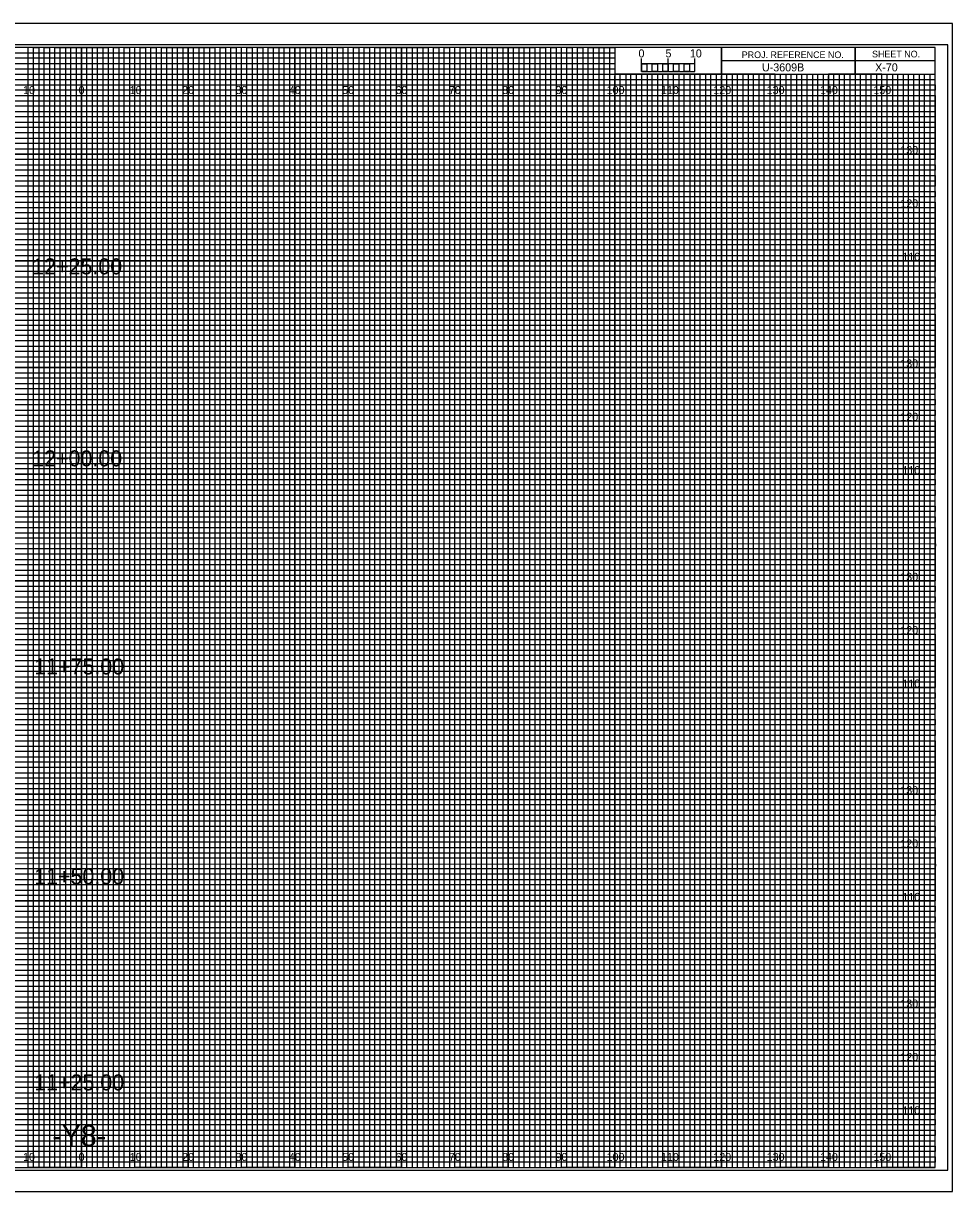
# Model space of a CAD drawing. Extents: x -13 to 323, y -5 to 434.
# Drawn here: x 149.1 to 323.3, y -4.5 to 214.5 of the extents above; entities that cross this region are included whole.
import ezdxf

# ---------------------------------------------------------------- set-up
doc = ezdxf.new("R2010")
doc.units = 0
for name, color, linetype in [('Exist CMT Pavement', 7, 'Continuous'), ('Exist Cross Section Cell', 7, 'Continuous'), ('Exist XS Center Line Elevation Label', 7, 'Continuous'), ('Exist XS Ground Line', 7, 'Continuous'), ('Prop CMT Pvmt Course 1 Wedge', 7, 'Continuous'), ('Prop CMT Pvmt Course 2', 7, 'Continuous'), ('Prop CMT Pvmt Course 2 Wedge', 7, 'Continuous'), ('Prop CMT Pvmt Course 3', 7, 'Continuous'), ('Prop CMT Pvmt Course 3 Wedge', 7, 'Continuous'), ('Prop CMT Pvmt Surface', 7, 'Continuous'), ('Prop CMT Pvmt Wedge Surface 1', 7, 'Continuous'), ('Prop CMT Pvmt Wedge Surface 2', 7, 'Continuous'), ('Prop CMT Shld Paved Course 1', 7, 'Continuous'), ('Prop CMT Shld Paved Course 2', 7, 'Continuous'), ('Prop CMT Shld Paved Course 3', 7, 'Continuous'), ('Prop CMT Subgrade Earthwork', 7, 'Continuous'), ('Scratch_Level_0', 7, 'Continuous')]:
    doc.layers.add(name, color=color, linetype=linetype)

msp = doc.modelspace()

# ---------------------------------------------------------------- linework, layer by layer
at = {"layer": 'Exist XS Center Line Elevation Label'}
for points in [[(145, 0), (155, 0), (155, 210), (165, 210), (165, 0), (175, 0), (175, 210), (185, 210), (185, 0), (195, 0), (195, 210), (205, 210), (205, 0), (215, 0), (215, 210), (225, 210), (225, 0), (235, 0), (235, 210), (245, 210), (245, 0), (255, 0), (255, 210), (259.93, 210), (260, 210), (260, 205), (264.99, 205), (264.99, 0), (275, 0), (275, 205), (285, 205), (285, 0), (295, 0), (295, 205), (305, 205), (305, 0), (315, 0), (315, 205)], [(0, 205), (275, 205)], [(0, 185), (320, 185), (320, 195), (0, 195)], [(0, 165), (320, 165), (320, 175), (0, 175)], [(0, 145), (320, 145), (320, 155), (0, 155)], [(0, 125), (320, 125), (320, 135), (0, 135)], [(0, 105), (320, 105), (320, 115), (0, 115)], [(0, 85), (320, 85), (320, 95), (0, 95)], [(0, 65), (320, 65), (320, 75), (0, 75)], [(0, 45), (320, 45), (320, 55), (0, 55)], [(0, 25), (320, 25), (320, 35), (0, 35)], [(0, 5), (320, 5), (320, 15), (0, 15)]]:
    msp.add_lwpolyline(points, dxfattribs=at)
at = {"layer": 'Exist XS Ground Line'}
for p, q in [((150, 210), (140, 210)), ((150, 0), (150, 210)), ((170, 210), (160, 210)), ((160, 210), (160, 0)), ((170, 0), (170, 210)), ((190, 210), (180, 210)), ((180, 210), (180, 0)), ((190, 0), (190, 210)), ((210, 210), (200, 210)), ((200, 210), (200, 0)), ((210, 0), (210, 210)), ((230, 210), (220, 210)), ((220, 210), (220, 0)), ((230, 0), (230, 210)), ((250, 210), (240, 210)), ((240, 210), (240, 0)), ((250, 0), (250, 210)), ((260, 210), (260, 0)), ((270, 0), (270, 205)), ((290, 205), (280, 205)), ((280, 205), (280, 0)), ((290, 0), (290, 205)), ((310, 205), (300, 205)), ((300, 205), (300, 0)), ((310, 0), (310, 205)), ((160, 0), (150, 0)), ((180, 0), (170, 0)), ((200, 0), (190, 0)), ((220, 0), (210, 0)), ((240, 0), (230, 0)), ((260, 0), (250, 0)), ((280, 0), (270, 0)), ((300, 0), (290, 0)), ((320, 0), (310, 0)), ((320, 0), (320, 0))]:
    msp.add_line(p, q, dxfattribs=at)
for points in [[(0, 200), (320, 200), (320, 190), (0, 190)], [(0, 180), (320, 180), (320, 170), (0, 170)], [(0, 160), (320, 160), (320, 150), (0, 150)], [(0, 140), (320, 140), (320, 130), (0, 130)], [(0, 120), (320, 120), (320, 110), (0, 110)], [(0, 100), (320, 100), (320, 90), (0, 90)], [(0, 80), (320, 80), (320, 70), (0, 70)], [(0, 60), (320, 60), (320, 50), (0, 50)], [(0, 40), (320, 40), (320, 30), (0, 30)], [(0, 20), (320, 20), (320, 10), (0, 10)]]:
    msp.add_lwpolyline(points, dxfattribs=at)
at = {"layer": 'Prop CMT Pvmt Course 1 Wedge'}
for p, q in [((323.3, 214.5), (-13.4, 214.5)), ((-13.4, -4.5), (323.3, -4.5))]:
    msp.add_line(p, q, dxfattribs=at)
at = {"layer": 'Prop CMT Pvmt Course 2'}
msp.add_lwpolyline([(-13.4, -4.5), (323.3, -4.5), (323.3, 214.5), (-13.4, 214.5)], close=True, dxfattribs=at)
at = {"layer": 'Prop CMT Pvmt Course 3'}
msp.add_lwpolyline([(-10.8, -0.5), (322.4, -0.5), (322.4, 210.5), (-10.8, 210.5)], close=True, dxfattribs=at)
at = {"layer": 'Prop CMT Shld Paved Course 1'}
for p, q in [((305, 210), (305, 205)), ((305, 205), (305, 210)), ((280, 207.5), (280, 205)), ((320, 207.49), (280, 207.49)), ((280, 205), (320, 205))]:
    msp.add_line(p, q, dxfattribs=at)
for points in [[(320, 210), (0, 210), (0, 0), (320, 0)], [(280, 210), (260, 210), (260, 205.03), (280, 205.03)], [(320, 210), (280, 210), (280, 205), (320, 205)]]:
    msp.add_lwpolyline(points, close=True, dxfattribs=at)
at = {"layer": 'Prop CMT Shld Paved Course 2'}
for p, q in [((267, 205), (266.01, 205)), ((266.01, 205), (266.01, 0)), ((267, 0), (267, 205)), ((269, 205), (268, 205)), ((268, 205), (268, 0)), ((269, 0), (269, 205)), ((266.01, 0), (265, 0)), ((268, 0), (267, 0))]:
    msp.add_line(p, q, dxfattribs=at)
for points in [[(150, 0), (151, 0), (151, 210), (152, 210), (152, 0)], [(152, 0), (153, 0), (153, 210), (154, 210), (154, 0)], [(155, 0), (156, 0), (156, 210), (157, 210), (157, 0)], [(157, 0), (158, 0), (158, 210), (159, 210), (159, 0)], [(160, 0), (161, 0), (161, 210), (162, 210), (162, 0)], [(162, 0), (163, 0), (163, 210), (164, 210), (164, 0)], [(165, 0), (166, 0), (166, 210), (167, 210), (167, 0)], [(167, 0), (168, 0), (168, 210), (169, 210), (169, 0)], [(170, 0), (171, 0), (171, 210), (172, 210), (172, 0)], [(172, 0), (173, 0), (173, 210), (174, 210), (174, 0)], [(175, 0), (176, 0), (176, 210), (177, 210), (177, 0)], [(177, 0), (178, 0), (178, 210), (179, 210), (179, 0)], [(180, 0), (181, 0), (181, 210), (182, 210), (182, 0)], [(182, 0), (183, 0), (183, 210), (184, 210), (184, 0)], [(185, 0), (186, 0), (186, 210), (187, 210), (187, 0)], [(187, 0), (188, 0), (188, 210), (189, 210), (189, 0)], [(190, 0), (191, 0), (191, 210), (192, 210), (192, 0)], [(192, 0), (193, 0), (193, 210), (194, 210), (194, 0)], [(195, 0), (196, 0), (196, 210), (197, 210), (197, 0)], [(197, 0), (198, 0), (198, 210), (199, 210), (199, 0)], [(200, 0), (201, 0), (201, 210), (202, 210), (202, 0)], [(202, 0), (203, 0), (203, 210), (204, 210), (204, 0)], [(205, 0), (206, 0), (206, 210), (207, 210), (207, 0)], [(207, 0), (208, 0), (208, 210), (209, 210), (209, 0)], [(210, 0), (211, 0), (211, 210), (212, 210), (212, 0)], [(212, 0), (213, 0), (213, 210), (214, 210), (214, 0)], [(215, 0), (216, 0), (216, 210), (217, 210), (217, 0)], [(217, 0), (218, 0), (218, 210), (219, 210), (219, 0)], [(220, 0), (221, 0), (221, 210), (222, 210), (222, 0)], [(222, 0), (223, 0), (223, 210), (224, 210), (224, 0)], [(225, 0), (226, 0), (226, 210), (227, 210), (227, 0)], [(227, 0), (228, 0), (228, 210), (229, 210), (229, 0)], [(230, 0), (231, 0), (231, 210), (232, 210), (232, 0)], [(232, 0), (233, 0), (233, 210), (234, 210), (234, 0)], [(235, 0), (236, 0), (236, 210), (237, 210), (237, 0)], [(237, 0), (238, 0), (238, 210), (239, 210), (239, 0)], [(240, 0), (241, 0), (241, 210), (242, 210), (242, 0)], [(242, 0), (243, 0), (243, 210), (244, 210), (244, 0)], [(245, 0), (246, 0), (246, 210), (247, 210), (247, 0)], [(247, 0), (248, 0), (248, 210), (249, 210), (249, 0)], [(250, 0), (251, 0), (251, 210), (252, 210), (252, 0)], [(252, 0), (253, 0), (253, 210), (254, 210), (254, 0)], [(255, 0), (256, 0), (256, 210), (257, 210), (257, 0)], [(257, 0), (258, 0), (258, 210), (259, 210), (259, 0)], [(260, 0), (261, 0), (261, 205), (262.02, 205), (262.02, 0)], [(262, 0), (263, 0), (263, 205), (263.99, 205), (263.99, 0)], [(270, 0), (270.98, 0), (270.98, 205), (272, 205), (272, 0)], [(272, 0), (273, 0), (273, 205), (274.05, 205), (274.05, 0)], [(275, 0), (276, 0), (276, 205), (277, 205), (277, 0)], [(277, 0), (278, 0), (278, 205), (279, 205), (279, 0)], [(280, 0), (281, 0), (281, 205), (282, 205), (282, 0)], [(282, 0), (283, 0), (283, 205), (284, 205), (284, 0)], [(285, 0), (286, 0), (286, 205), (287, 205), (287, 0)], [(287, 0), (288, 0), (288, 205), (289, 205), (289, 0)], [(290, 0), (291, 0), (291, 205), (292, 205), (292, 0)], [(292, 0), (293, 0), (293, 205), (294, 205), (294, 0)], [(295, 0), (296, 0), (296, 205), (297, 205), (297, 0)], [(297, 0), (298, 0), (298, 205), (299, 205), (299, 0)], [(300, 0), (301, 0), (301, 205), (302, 205), (302, 0)], [(302, 0), (303, 0), (303, 205), (304, 205), (304, 0)], [(305, 0), (306, 0), (306, 205), (307, 205), (307, 0)], [(307, 0), (308, 0), (308, 205), (309, 205), (309, 0)], [(310, 0), (311, 0), (311, 205), (312, 205), (312, 0)], [(312, 0), (313, 0), (313, 205), (314, 205), (314, 0)], [(315, 0), (316, 0), (316, 205), (317, 205), (317, 0)], [(317, 0), (318, 0), (318, 205), (319, 205), (319, 0)]]:
    msp.add_lwpolyline(points, dxfattribs=at)
at = {"layer": 'Prop CMT Shld Paved Course 3'}
for p, q in [((265, 205.49), (265, 207.9)), ((265, 206.9), (265, 207.9)), ((270, 205.49), (270, 207.9)), ((275, 205.49), (275, 207.9)), ((275, 206.9), (275, 207.9))]:
    msp.add_line(p, q, dxfattribs=at)
for points in [[(275, 206.9), (265, 206.9), (265, 205.49), (275, 205.49)], [(265, 206.9), (266, 206.9), (266, 205.49), (265, 205.49)], [(267, 206.9), (268, 206.9), (268, 205.49), (267, 205.49)], [(269, 206.9), (270, 206.9), (270, 205.49), (269, 205.49)], [(271, 206.9), (272, 206.9), (272, 205.49), (271, 205.49)], [(273, 206.9), (274, 206.9), (274, 205.49), (273, 205.49)]]:
    msp.add_lwpolyline(points, close=True, dxfattribs=at)
at = {"layer": 'Prop CMT Subgrade Earthwork'}
for p, q in [((150, 0), (150, 210)), ((160, 0), (160, 210)), ((170, 0), (170, 210)), ((180, 0), (180, 210)), ((190, 0), (190, 210)), ((200, 0), (200, 210)), ((210, 0), (210, 210)), ((220, 0), (220, 210)), ((230, 0), (230, 210)), ((240, 0), (240, 210)), ((250, 0), (250, 210)), ((260, 0), (260, 204.69)), ((270, 0), (270, 204.69)), ((280, 0), (280, 204.69)), ((290, 0), (290, 204.69)), ((300, 0), (300, 204.69)), ((310, 0), (310, 204.69)), ((0, 200), (320, 200)), ((0, 190), (320, 190)), ((0, 180), (320, 180)), ((0, 170), (320, 170)), ((0, 160), (320, 160)), ((0, 150), (320, 150)), ((0, 140), (320, 140)), ((0, 130), (320, 130)), ((0, 120), (320, 120)), ((0, 110), (320, 110)), ((0, 100), (320, 100)), ((0, 90), (320, 90)), ((0, 80), (320, 80)), ((0, 70), (320, 70)), ((0, 60), (320, 60)), ((0, 50), (320, 50)), ((0, 40), (320, 40)), ((0, 30), (320, 30)), ((0, 20), (320, 20)), ((0, 10), (320, 10))]:
    msp.add_line(p, q, dxfattribs=at)
at = {"layer": 'Scratch_Level_0'}
for p, q in [((0, 209), (260, 209)), ((260, 209), (260, 207.98)), ((260, 207.98), (0, 207.98)), ((0, 207), (260, 207)), ((260, 205.89), (0, 205.89)), ((260, 207), (260, 205.89)), ((0, 204), (320, 204))]:
    msp.add_line(p, q, dxfattribs=at)
for points in [[(0, 203), (270, 203), (320, 203), (320, 202), (0, 202)], [(0, 201), (320, 201), (320, 199), (0, 199)], [(0, 198), (320, 198), (320, 197), (0, 196.98)], [(0, 196), (320, 196), (320, 194), (0, 194)], [(0, 193), (320, 193), (320, 192), (0, 192)], [(0, 191), (320, 191), (320, 189), (0, 189)], [(0, 188), (320, 188), (320, 187), (0, 187)], [(0, 186), (320, 186), (320, 184), (0, 184)], [(0, 183), (320, 183), (320, 182), (0, 182)], [(0, 181), (320, 181), (320, 179), (0, 179)], [(0, 178), (320, 178), (320, 177), (0, 177)], [(0, 176), (320, 176), (320, 173.95), (320, 173), (320, 172), (0, 172)], [(0, 174), (320, 174), (320, 173), (0, 173)], [(0, 171), (320, 171), (320, 169), (0, 169.03)], [(0, 169.03), (320, 169), (320, 168), (0, 168)], [(0, 167), (320, 167), (320, 166), (0, 166)], [(0, 164), (320, 164), (320, 163), (0, 163)], [(0, 162), (320, 162), (320, 161), (0, 161)], [(-0.07, 158.89), (320, 158.89), (320, 157.88), (-0.07, 157.88)], [(0, 157), (320, 157), (320, 156), (0, 156)], [(0, 154), (320, 154), (320, 153), (0, 153)], [(0, 152), (320, 152), (320, 151), (0, 151)], [(0, 149), (320, 149), (320, 148), (0, 148)], [(0, 147), (320, 147), (320, 146), (0, 146)], [(0, 144), (320, 144), (320, 143), (0, 143)], [(0, 142), (320, 142), (320, 141), (0, 141)], [(0, 139), (320, 139), (319.99, 137.98), (0, 138)], [(0, 137), (320, 137), (320, 136), (0, 136)], [(0, 134), (320, 134), (320, 133), (0, 133)], [(0, 132), (320, 132), (320, 131), (0, 131)], [(0, 129), (320, 129), (320, 128), (0, 128)], [(0, 127), (320, 127), (320, 126), (0, 126)], [(0, 124), (320, 124), (320, 123), (0, 123)], [(0, 122), (320, 122), (320, 121), (0, 121)], [(0, 119), (320, 119), (320, 118), (0, 118)], [(0, 116.99), (320.07, 116.91), (320, 116), (0, 116)], [(0, 114), (320, 114), (320, 113), (0, 113)], [(0, 112), (320, 112), (320, 111), (0, 111)], [(0, 109), (320, 109), (320, 108), (0, 108)], [(0, 107), (320, 107), (320, 106), (0, 106)], [(0, 104), (320, 104), (320, 103), (0, 103)], [(0, 102), (320, 102), (320, 101), (0, 101)], [(0, 99), (320, 99), (320, 98), (0, 98)], [(0, 97), (320, 97), (320, 96), (0, 96)], [(0, 94), (320, 94), (320, 93), (0, 93)], [(0, 92), (320, 92), (320, 91), (0, 91)], [(0, 89), (320, 89), (320, 88), (0, 88)], [(0, 87), (320, 87), (320, 86), (0, 86)], [(0, 84), (320, 84), (320, 83), (0, 83)], [(0, 82), (320, 82), (320, 81), (0, 81)], [(0, 79), (320, 79), (319.99, 77.98), (0, 78)], [(0, 77), (320, 77), (320, 76), (0, 76)], [(0, 74), (320, 74), (320, 73), (0, 73)], [(0, 72), (320, 72), (320, 71), (0, 71)], [(0, 69), (320, 69), (320, 68), (0, 68)], [(0, 67), (320, 67), (320, 66), (0, 66)], [(0, 64), (320, 64), (320, 63), (0, 63)], [(0, 62), (320, 62), (320, 61), (0, 61)], [(0, 59), (320, 59), (320, 58), (0, 58)], [(0, 56.99), (320.07, 56.91), (320, 56), (0, 56)], [(0, 54), (320, 54), (320, 53), (0, 53)], [(0, 52), (320, 52), (320, 51), (0, 51)], [(0, 49), (320, 49), (320, 48), (0, 48)], [(0, 47), (320, 47), (320, 46), (0, 46)], [(0, 44), (320, 44), (320, 43), (0, 43)], [(0, 42), (320, 42), (320, 41), (0, 41)], [(0, 39), (320, 39), (320, 38), (0, 38)], [(0, 37), (320, 37), (320, 36), (0, 36)], [(0, 34), (320, 34), (320, 33), (0, 33)], [(0, 32), (320, 32), (320, 31), (0, 31)], [(0, 29), (320, 29), (320, 28), (0, 28)], [(0, 27), (320, 27), (320, 26), (0, 26)], [(0, 24), (320, 24), (320, 23), (0, 23)], [(0, 22), (320, 22), (320, 21), (0, 21)], [(0, 19), (320, 19), (320, 18), (0, 18)], [(0, 17), (320, 17), (320, 16), (0, 16)], [(0, 14), (320, 14), (320, 13), (0, 13)], [(0, 12), (320, 12), (320, 11), (0, 11)], [(0, 9), (320, 9), (320, 8), (0, 8)], [(0, 7), (320, 7), (320, 6), (0, 6)], [(0, 4), (320, 4), (320, 3), (0, 3)], [(0, 2), (320, 2), (320, 1), (0, 1)]]:
    msp.add_lwpolyline(points, dxfattribs=at)

# ---------------------------------------------------------------- texts
at = {"layer": 'Exist CMT Pavement'}
msp.add_text('X-70', height=1.5, dxfattribs=at).set_placement((308.77, 205.5))
at = {"layer": 'Exist Cross Section Cell'}
for s, p in [('10', (149.04, 201.25)), ('0', (159.45, 201.25)), ('0', (159.45, 201.25)), ('10', (169.04, 201.25)), ('20', (178.86, 201.25)), ('30', (188.86, 201.25)), ('40', (198.86, 201.25)), ('50', (208.86, 201.25)), ('60', (218.86, 201.25)), ('70', (228.86, 201.25)), ('80', (238.86, 201.25)), ('90', (248.86, 201.25)), ('100', (258.44, 201.25)), ('110', (268.62, 201.25)), ('120', (278.44, 201.25)), ('130', (288.44, 201.25)), ('140', (298.44, 201.25)), ('150', (308.44, 201.25)), ('10', (149.04, 1.25)), ('0', (159.45, 1.25)), ('0', (159.45, 1.25)), ('10', (169.04, 1.25)), ('20', (178.86, 1.25)), ('30', (188.86, 1.25)), ('40', (198.86, 1.25)), ('50', (208.86, 1.25)), ('60', (218.86, 1.25)), ('70', (228.86, 1.25)), ('80', (238.86, 1.25)), ('90', (248.86, 1.25)), ('100', (258.44, 1.25)), ('110', (268.62, 1.25)), ('120', (278.44, 1.25)), ('130', (288.44, 1.25)), ('140', (298.44, 1.25)), ('150', (308.44, 1.25))]:
    msp.add_text(s, height=1.5, dxfattribs=at).set_placement(p)
at = {"layer": 'Prop CMT Pvmt Course 2 Wedge'}
for s, p in [('130', (313.49, 190)), ('120', (313.5, 180)), ('110', (313.88, 170)), ('130', (313.49, 150)), ('120', (313.5, 140)), ('110', (313.88, 130)), ('130', (313.49, 110)), ('120', (313.5, 100)), ('110', (313.88, 90)), ('130', (313.49, 70)), ('120', (313.5, 60)), ('110', (313.88, 50)), ('130', (313.49, 30)), ('120', (313.5, 20)), ('110', (313.88, 10))]:
    msp.add_text(s, height=1.5, dxfattribs=at).set_placement(p)
at = {"layer": 'Prop CMT Pvmt Course 3 Wedge'}
for s, p in [('12+25.00', (150.77, 167.45)), ('12+00.00', (150.77, 131.46)), ('11+75.00', (151.13, 92.45)), ('11+50.00', (151.13, 53.11)), ('11+25.00', (151.13, 14.48))]:
    msp.add_text(s, height=3, dxfattribs=at).set_placement(p)
at = {"layer": 'Prop CMT Pvmt Surface'}
msp.add_text('U-3609B', height=1.5, dxfattribs=at).set_placement((287.56, 205.5))
at = {"layer": 'Prop CMT Pvmt Wedge Surface 1'}
msp.add_text('-Y8-', height=4, dxfattribs=at).set_placement((154.52, 4))
at = {"layer": 'Prop CMT Pvmt Wedge Surface 2'}
for s, p in [('5', (269.47, 208.12)), ('10', (274.04, 208.12))]:
    msp.add_text(s, height=1.5, dxfattribs=at).set_placement(p)
at = {"layer": 'Prop CMT Shld Paved Course 1'}
for s, p in [('PROJ. REFERENCE NO.', (283.77, 207.99)), ('SHEET NO.', (308.19, 208.12))]:
    msp.add_text(s, height=1.25, dxfattribs=at).set_placement(p)
at = {"layer": 'Prop CMT Shld Paved Course 3'}
msp.add_text('0', height=1.5, dxfattribs=at).set_placement((264.41, 208.12))

doc.saveas('drawing.dxf')
